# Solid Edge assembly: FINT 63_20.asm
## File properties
Title: Zylinder
Author: bmolnar
Template: iso assembly.asm
Last saved by: bmolnar
Revision: 12
Application: Solid Edge
Username: bmolnar
Dokumentum tartalom típus: 1
Document Number: FINT 63/20
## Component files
hrungsstange.par
Profilrohr.par
Platte.par
Kolbenstange.par
Kit_1.par
Kit_2.par
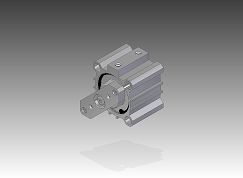
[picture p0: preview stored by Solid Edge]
